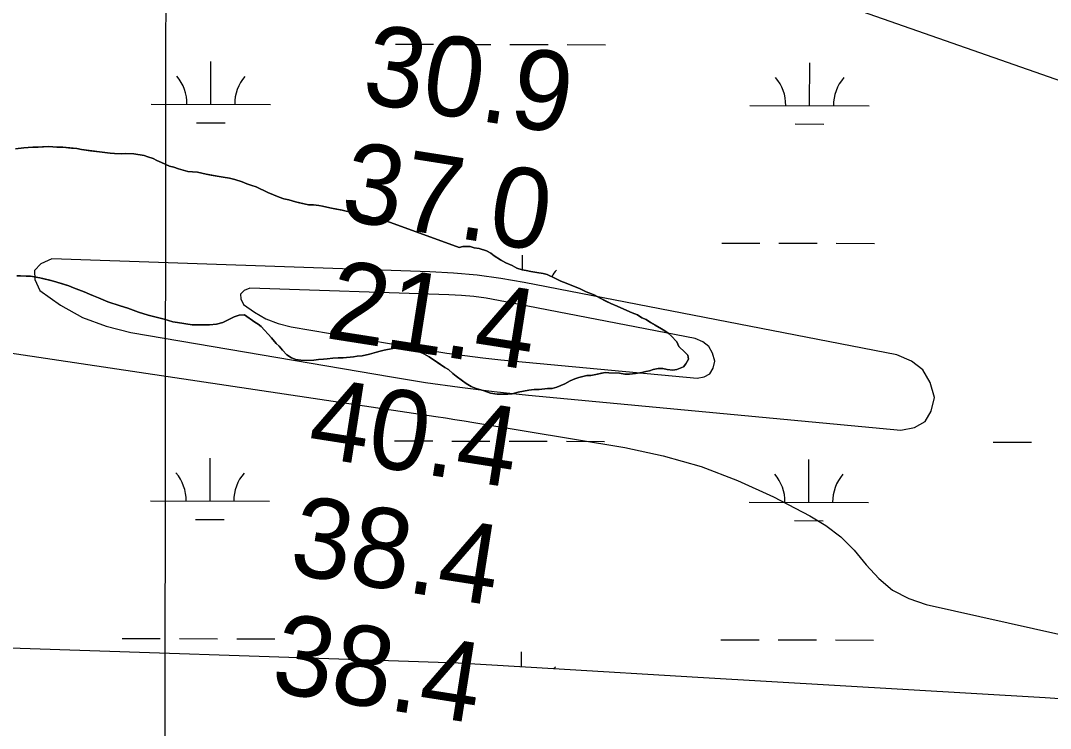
# Model space of a CAD drawing. Extents: x 3219052 to 3256913, y 800770 to 826146.
# Drawn here: x 3233583 to 3234446, y 813174 to 813768 of the extents above; entities that cross this region are included whole.
import ezdxf

# ---------------------------------------------------------------- set-up
doc = ezdxf.new("R2010")
doc.units = 0
for name, color, linetype in [('V-GRID-MAJR', 7, 'Continuous'), ('V-RIVR-RANG', 7, 'Continuous'), ('V-SITE-VEGE', 7, 'Continuous'), ('V-TOPO-MAJR', 7, 'Continuous'), ('V-TOPO-MINR', 7, 'Continuous'), ('V-TOPO-SHOR', 7, 'Continuous'), ('V-WETL-SWMP', 7, 'Continuous')]:
    doc.layers.add(name, color=color, linetype=linetype)

msp = doc.modelspace()

# ---------------------------------------------------------------- linework, layer by layer
at = {"layer": 'V-GRID-MAJR'}
msp.add_spline([(3233694.76, 806171.3), (3233702.69, 812230.43), (3233710.62, 818292.64), (3233718.56, 824354.89), (3233718.56, 824357.93)], degree=3, dxfattribs=at)
at = {"layer": 'V-SITE-VEGE'}
for points in [[(3233950.31, 813577.73), (3233886.64, 813600.99), (3233877.88, 813602.74), (3233873.82, 813604.08), (3233860.68, 813607.17), (3233855.67, 813608.21), (3233852.23, 813609.22), (3233843.14, 813610.66), (3233839.39, 813611.68), (3233832.5, 813613.07), (3233828.11, 813613.47), (3233824.02, 813613.56), (3233813.07, 813615.97), (3233807.44, 813617.66), (3233803.38, 813618.68), (3233799.32, 813620.02), (3233789.96, 813623.97), (3233780, 813628.57), (3233776.56, 813629.9), (3233772.19, 813631.24), (3233768.45, 813632.89), (3233762.21, 813634.9), (3233757.82, 813635.93), (3233752.5, 813636.66), (3233749.05, 813637.36), (3233738.08, 813639.15), (3233730.89, 813640.86), (3233722.73, 813641.65), (3233714.91, 813643.7), (3233711.17, 813645.03), (3233707.42, 813646.04), (3233700.87, 813649), (3233696.82, 813650.66), (3233693.71, 813652.29), (3233689.34, 813653.95), (3233686.22, 813654.95), (3233677.44, 813656.39), (3233670.84, 813656.52), (3233667.07, 813656.27), (3233661.42, 813656.7), (3233657.65, 813656.78), (3233648.87, 813657.89), (3233633.82, 813660.08), (3233629.75, 813660.79), (3233618.14, 813661.96), (3233613.11, 813662.06), (3233606.21, 813662.51), (3233585.44, 813661.35), (3233578.5, 813660.55)], [(3233832.45, 813483.88), (3233839.69, 813484.36), (3233844.42, 813484.9), (3233852.92, 813485.35), (3233861.73, 813486.12), (3233864.89, 813486.69), (3233868.98, 813486.92), (3233874.98, 813488.38), (3233880.99, 813490.14), (3233884.14, 813490.71), (3233887.3, 813491.59), (3233894.56, 813493.02), (3233900.23, 813493.53), (3233906.19, 813493.1), (3233910.58, 813492.39), (3233914.95, 813491.04), (3233920.57, 813488.73), (3233925.23, 813486.12), (3233938.25, 813477.06), (3233941.36, 813475.43), (3233945.07, 813472.21), (3233947.86, 813469.96), (3233956.22, 813463.82), (3233960.26, 813461.22), (3233964.62, 813459.56), (3233971.19, 813457.54), (3233976.49, 813455.56), (3233982.13, 813454.81), (3233990.93, 813454.64), (3233994.71, 813455.19), (3233999.77, 813456.35), (3234008.6, 813458.06), (3234013.02, 813458.6), (3234017.42, 813458.83), (3234024.35, 813459.64), (3234028.12, 813459.56), (3234032.23, 813460.73), (3234038.89, 813463.43), (3234043.34, 813465.86), (3234047.15, 813467.67), (3234050.63, 813468.86), (3234057.26, 813470.3), (3234060.72, 813470.55), (3234064.82, 813471.41), (3234072.71, 813472.82), (3234075.85, 813472.76), (3234084.64, 813472.27), (3234089.03, 813471.56), (3234093.11, 813471.47), (3234098.15, 813472), (3234103.51, 813472.84), (3234106.68, 813473.72), (3234109.83, 813474.29), (3234113, 813475.48), (3234117.1, 813476.34), (3234120.87, 813476.27), (3234124.63, 813475.57), (3234129.33, 813474.84), (3234132.8, 813475.4), (3234138.19, 813477.81), (3234140.13, 813480.29), (3234142.4, 813484.01), (3234141.84, 813487.48), (3234139.38, 813490.04), (3234134.44, 813494.86), (3234132.63, 813498.67), (3234128.02, 813503.79), (3234125.55, 813506.04), (3234122.76, 813507.98), (3234110.64, 813514.82), (3234106.91, 813517.41), (3234103.48, 813518.73), (3234099.76, 813521.32), (3234095.39, 813522.98), (3234090.72, 813524.96), (3234077.32, 813530.88), (3234067.98, 813535.47), (3234063.94, 813537.75), (3234061.14, 813539.06), (3234056.77, 813540.72), (3234051.16, 813543.35), (3234047.42, 813544.68), (3234039.94, 813547.97), (3234035.57, 813549.63), (3234030.58, 813551.93), (3234024.05, 813555.2), (3234015.28, 813556.95), (3234010.27, 813557.68), (3234003.06, 813559.08), (3233998.69, 813560.42), (3233994.65, 813562.7), (3233989.35, 813565.01), (3233984.99, 813567.3), (3233979.72, 813570.86), (3233976.94, 813573.11), (3233973.2, 813575.07), (3233966.96, 813577.08), (3233962.88, 813577.48), (3233959.44, 813578.49), (3233953.47, 813578.61), (3233950.31, 813577.73)], [(3233579.54, 813553.96), (3233590.85, 813553.74), (3233598.68, 813552.33), (3233610.25, 813549.58), (3233623.06, 813545.56), (3233627.12, 813543.9), (3233635.85, 813540.59), (3233643.65, 813537.29), (3233648.01, 813535.63), (3233655.81, 813532.33), (3233666.12, 813528.98), (3233672.67, 813526.97), (3233681.41, 813523.65), (3233689.53, 813520.97), (3233698.61, 813518.91), (3233702.98, 813517.56), (3233710.17, 813515.54), (3233714.24, 813514.83), (3233726.46, 813513.02), (3233736.21, 813512.82), (3233740.93, 813513.04), (3233746.91, 813513.55), (3233752.28, 813515.01), (3233761.8, 813519.54), (3233765.92, 813521.03), (3233770.33, 813521.26), (3233779, 813515.11), (3233781.8, 813513.49), (3233784.28, 813511.55), (3233792.89, 813501.95), (3233796.88, 813497.16), (3233799.35, 813494.9), (3233802.11, 813491.71), (3233805.81, 813487.86), (3233809.85, 813485.27), (3233813.28, 813483.94), (3233817.67, 813483.22), (3233822.69, 813483.13), (3233828.35, 813483.33), (3233832.45, 813483.88)]]:
    msp.add_lwpolyline(points, dxfattribs=at)
at = {"layer": 'V-TOPO-MAJR'}
msp.add_lwpolyline([(3233950.8, 813460.53), (3233979.53, 813457.06), (3234008.33, 813454.02), (3234320.46, 813424.64), (3234331.9, 813426.92), (3234340.83, 813431.79), (3234345.99, 813440.56), (3234348.64, 813451.92), (3234345.07, 813464.65), (3234339.05, 813475.22), (3234329.35, 813482.57), (3234317.2, 813487.78), (3234004.79, 813548.52), (3233985.15, 813551.86), (3233965.43, 813554.57), (3233945.61, 813556.34), (3233925.72, 813557.48), (3233608.84, 813568.14), (3233599.73, 813564.06), (3233594.39, 813558.54), (3233594.69, 813550.87), (3233598.76, 813541.75), (3233616.17, 813529.43), (3233634.51, 813519.13), (3233654.24, 813511.85), (3233674.91, 813506.58), (3233893.55, 813469.21), (3233922.15, 813464.66), (3233950.8, 813460.53)], dxfattribs=at)
at = {"layer": 'V-TOPO-MINR'}
for points in [[(3233954.92, 813487.1), (3233970.06, 813485.27), (3233985.24, 813483.67), (3234149.71, 813468.19), (3234155.74, 813469.39), (3234160.45, 813471.96), (3234163.17, 813476.58), (3234164.56, 813482.56), (3234162.68, 813489.27), (3234159.51, 813494.84), (3234154.39, 813498.72), (3234147.99, 813501.46), (3233983.37, 813533.47), (3233973.02, 813535.23), (3233962.63, 813536.66), (3233952.19, 813537.59), (3233941.7, 813538.19), (3233774.73, 813543.81), (3233769.92, 813541.66), (3233767.11, 813538.75), (3233767.27, 813534.7), (3233769.42, 813529.9), (3233778.59, 813523.41), (3233788.25, 813517.98), (3233798.65, 813514.14), (3233809.55, 813511.37), (3233924.75, 813491.68), (3233939.82, 813489.28), (3233954.92, 813487.1)], [(3233506.07, 813499.63), (3233930.82, 813436.08), (3233938.74, 813434.87), (3233946.66, 813433.64), (3233954.57, 813432.38), (3233962.48, 813431.08), (3234089.1, 813410.07), (3234121.4, 813403.13), (3234153.04, 813394.23), (3234183.71, 813382.39), (3234213.72, 813368.58), (3234244.1, 813352.83), (3234257.66, 813344.52), (3234270.26, 813335.09), (3234281.39, 813323.98), (3234291.55, 813311.74), (3234301.98, 813300.17), (3234313.63, 813290.46), (3234327.12, 813283.52), (3234341.84, 813278.43), (3234545.44, 813232.72)]]:
    msp.add_lwpolyline(points, dxfattribs=at)
at = {"layer": 'V-TOPO-SHOR'}
for points in [[(3233578.5, 813660.55), (3233585.44, 813661.35), (3233588.9, 813661.6), (3233592.99, 813661.83), (3233597.4, 813662.06), (3233606.21, 813662.51), (3233613.11, 813662.06), (3233618.14, 813661.96), (3233625.35, 813661.19), (3233629.75, 813660.79), (3233633.82, 813660.08), (3233641.34, 813658.99), (3233648.87, 813657.89), (3233657.65, 813656.78), (3233661.42, 813656.7), (3233667.07, 813656.27), (3233670.84, 813656.52), (3233677.44, 813656.39), (3233686.22, 813654.95), (3233689.34, 813653.95), (3233693.71, 813652.29), (3233696.82, 813650.66), (3233700.87, 813649), (3233707.42, 813646.04), (3233711.17, 813645.03), (3233714.91, 813643.7), (3233718.98, 813642.67), (3233722.73, 813641.65), (3233726.81, 813641.26), (3233730.89, 813640.86), (3233738.08, 813639.15), (3233742.47, 813638.43), (3233749.05, 813637.36), (3233752.5, 813636.66), (3233757.82, 813635.93), (3233762.21, 813634.9), (3233768.45, 813632.89), (3233772.19, 813631.24), (3233776.56, 813629.9), (3233780, 813628.57), (3233789.96, 813623.97), (3233799.32, 813620.02), (3233803.38, 813618.68), (3233807.44, 813617.66), (3233813.07, 813615.97), (3233816.51, 813615.27), (3233824.02, 813613.56), (3233828.11, 813613.47), (3233832.5, 813613.07), (3233835.63, 813612.38), (3233839.39, 813611.68), (3233843.14, 813610.66)], [(3233843.14, 813610.66), (3233847.53, 813609.94), (3233852.23, 813609.22), (3233855.67, 813608.21), (3233860.68, 813607.17), (3233866.31, 813605.8), (3233873.82, 813604.08), (3233877.88, 813602.74), (3233882.89, 813601.7), (3233886.64, 813600.99), (3233950.31, 813577.73)], [(3233950.31, 813577.73), (3233953.47, 813578.61), (3233959.44, 813578.49), (3233962.88, 813577.48), (3233966.96, 813577.08), (3233973.2, 813575.07), (3233976.94, 813573.11), (3233979.72, 813570.86), (3233984.99, 813567.3), (3233989.35, 813565.01), (3233994.65, 813562.7), (3233998.69, 813560.42), (3234003.06, 813559.08), (3234006.51, 813558.38), (3234010.27, 813557.68), (3234015.28, 813556.95), (3234020.6, 813555.9), (3234024.05, 813555.2), (3234030.58, 813551.93), (3234035.57, 813549.63), (3234039.94, 813547.97), (3234047.42, 813544.68), (3234051.16, 813543.35), (3234056.77, 813540.72), (3234061.14, 813539.06), (3234063.94, 813537.75), (3234067.98, 813535.47), (3234073.27, 813532.85), (3234077.32, 813530.88), (3234082.62, 813528.58), (3234090.72, 813524.96), (3234095.39, 813522.98), (3234099.76, 813521.32), (3234103.48, 813518.73), (3234106.91, 813517.41), (3234110.64, 813514.82), (3234114.68, 813512.54), (3234119.96, 813509.61), (3234122.76, 813507.98), (3234125.55, 813506.04), (3234128.02, 813503.79), (3234132.63, 813498.67), (3234134.44, 813494.86), (3234139.38, 813490.04), (3234141.84, 813487.48), (3234142.4, 813484.01), (3234140.13, 813480.29), (3234138.19, 813477.81), (3234132.8, 813475.4), (3234129.33, 813474.84), (3234124.63, 813475.57), (3234120.87, 813476.27), (3234117.1, 813476.34), (3234113, 813475.48), (3234109.83, 813474.29), (3234106.68, 813473.72), (3234103.51, 813472.84), (3234098.15, 813472), (3234093.11, 813471.47), (3234089.03, 813471.56), (3234084.64, 813472.27), (3234075.85, 813472.76), (3234072.71, 813472.82), (3234069.55, 813472.26), (3234064.82, 813471.41), (3234060.72, 813470.55), (3234057.26, 813470.3), (3234050.63, 813468.86), (3234047.15, 813467.67), (3234043.34, 813465.86), (3234038.89, 813463.43), (3234032.23, 813460.73), (3234028.12, 813459.56), (3234024.35, 813459.64), (3234017.42, 813458.83), (3234013.02, 813458.6), (3234008.6, 813458.06), (3234004.18, 813457.21), (3233999.77, 813456.35), (3233994.71, 813455.19), (3233990.93, 813454.64), (3233982.13, 813454.81), (3233976.49, 813455.56), (3233971.19, 813457.55), (3233964.62, 813459.56), (3233960.26, 813461.22), (3233956.22, 813463.82), (3233953.12, 813466.08), (3233947.86, 813469.96), (3233945.07, 813472.21), (3233941.36, 813475.43), (3233938.25, 813477.06), (3233934.53, 813479.65), (3233925.23, 813486.12), (3233920.57, 813488.73), (3233914.95, 813491.04), (3233910.58, 813492.39), (3233906.19, 813493.1), (3233900.23, 813493.53), (3233894.56, 813493.02), (3233887.3, 813491.59)], [(3233887.3, 813491.59), (3233884.14, 813490.71), (3233880.99, 813490.14), (3233874.98, 813488.38), (3233868.98, 813486.92), (3233864.89, 813486.69), (3233861.73, 813486.12), (3233852.92, 813485.35), (3233848.82, 813485.12), (3233844.42, 813484.9), (3233839.69, 813484.36), (3233836.54, 813484.11), (3233832.45, 813483.88), (3233828.35, 813483.33), (3233822.69, 813483.13), (3233817.67, 813483.22), (3233813.28, 813483.94), (3233809.85, 813485.27), (3233805.81, 813487.86), (3233802.11, 813491.71), (3233799.35, 813494.9), (3233796.88, 813497.16), (3233792.89, 813501.95), (3233784.28, 813511.55), (3233781.8, 813513.49), (3233779, 813515.11), (3233770.33, 813521.26), (3233765.92, 813521.03), (3233761.8, 813519.54), (3233752.28, 813515.01), (3233746.91, 813513.55), (3233740.93, 813513.04), (3233736.21, 813512.82), (3233726.46, 813513.01), (3233714.24, 813514.83), (3233710.17, 813515.54), (3233702.98, 813517.56), (3233698.61, 813518.91), (3233689.53, 813520.97), (3233681.41, 813523.65), (3233672.67, 813526.97), (3233666.12, 813528.98), (3233655.81, 813532.33), (3233651.75, 813533.98), (3233648.01, 813535.63), (3233643.65, 813537.29), (3233640.53, 813538.61), (3233635.85, 813540.59), (3233627.12, 813543.9), (3233623.06, 813545.56), (3233617.75, 813547.23), (3233610.25, 813549.58), (3233607.12, 813550.27), (3233598.68, 813552.33), (3233590.85, 813553.74), (3233587.39, 813553.81), (3233582.68, 813553.9), (3233579.54, 813553.96)]]:
    msp.add_lwpolyline(points, dxfattribs=at)
at = {"layer": 'V-WETL-SWMP'}
for p, q in [((3233896.8, 813748.25), (3233928.8, 813748.18)), ((3233944.8, 813748.15), (3233976.8, 813748.08)), ((3233992.8, 813748.05), (3234024.8, 813747.98)), ((3234040.8, 813747.95), (3234072.8, 813747.88)), ((3233742.1, 813697.83), (3233742.18, 813733.83)), ((3234244.01, 813696.78), (3234244.09, 813732.78)), ((3233692.1, 813697.94), (3233792.1, 813697.73)), ((3234194.01, 813696.88), (3234294.01, 813696.67)), ((3233730.07, 813682.43), (3233754.07, 813682.38)), ((3234231.98, 813681.37), (3234255.98, 813681.32)), ((3234170.36, 813581.5), (3234202.36, 813581.44)), ((3234218.36, 813581.4), (3234250.36, 813581.33)), ((3234266.36, 813581.3), (3234298.36, 813581.23)), ((3234003.25, 813559.02), (3234003.28, 813571.42)), ((3233896.1, 813415.58), (3233928.1, 813415.51)), ((3233944.1, 813415.48), (3233976.1, 813415.41)), ((3233992.1, 813415.37), (3234024.1, 813415.31)), ((3234040.1, 813415.27), (3234072.1, 813415.21)), ((3234398.01, 813414.52), (3234430.01, 813414.46)), ((3233741.41, 813365.16), (3233741.48, 813401.16)), ((3234243.31, 813364.11), (3234243.39, 813400.11)), ((3233691.41, 813365.26), (3233791.41, 813365.05)), ((3234193.31, 813364.21), (3234293.31, 813364)), ((3233729.37, 813349.75), (3233753.37, 813349.7)), ((3234231.28, 813348.7), (3234255.28, 813348.65)), ((3233667.76, 813249.88), (3233699.76, 813249.81)), ((3233715.76, 813249.78), (3233747.76, 813249.71)), ((3233763.76, 813249.68), (3233795.76, 813249.61)), ((3234169.66, 813248.83), (3234201.66, 813248.76)), ((3234217.66, 813248.73), (3234249.66, 813248.66)), ((3234265.66, 813248.63), (3234297.66, 813248.56)), ((3234002.55, 813226), (3234002.58, 813238.75))]:
    msp.add_line(p, q, dxfattribs=at)
for points in [[(3232589.14, 814286.39), (3233211.38, 813982.24), (3233471.85, 813837.41), (3233703.38, 813779.48), (3233963.85, 813779.48), (3234195.38, 813808.45), (3234484.8, 813707.06), (3234687.39, 813649.13), (3234861.03, 813692.58), (3235032.69, 813819.76), (3235126.63, 813828.41), (3235146.41, 813856.84), (3235150.45, 813909.83), (3234962.33, 813967.76), (3234788.68, 814083.62), (3234745.27, 814228.45), (3234774.21, 814329.84), (3234803.15, 814518.12)], [(3233950.31, 813577.73), (3233886.64, 813600.99), (3233882.89, 813601.7), (3233877.88, 813602.74), (3233873.82, 813604.08), (3233866.31, 813605.8), (3233860.67, 813607.17), (3233855.67, 813608.21), (3233852.23, 813609.22), (3233847.53, 813609.94), (3233843.14, 813610.66), (3233839.39, 813611.68), (3233835.63, 813612.38), (3233832.5, 813613.07), (3233828.11, 813613.47), (3233824.02, 813613.55), (3233816.51, 813615.27), (3233813.07, 813615.97), (3233807.44, 813617.66), (3233803.38, 813618.68), (3233799.32, 813620.02), (3233789.96, 813623.97), (3233780, 813628.57), (3233776.57, 813629.9), (3233772.19, 813631.24), (3233768.45, 813632.89), (3233762.21, 813634.9), (3233757.82, 813635.93), (3233752.5, 813636.66), (3233749.05, 813637.36), (3233742.47, 813638.43), (3233738.08, 813639.15), (3233730.89, 813640.86), (3233726.81, 813641.26), (3233722.73, 813641.65), (3233718.98, 813642.67), (3233714.91, 813643.7), (3233711.17, 813645.03), (3233707.42, 813646.04), (3233700.87, 813649), (3233696.82, 813650.66), (3233693.71, 813652.29), (3233689.34, 813653.95), (3233686.22, 813654.95), (3233677.44, 813656.38), (3233670.84, 813656.52), (3233667.07, 813656.28), (3233661.42, 813656.7), (3233657.65, 813656.78), (3233648.87, 813657.89), (3233641.34, 813658.99), (3233633.82, 813660.08), (3233629.75, 813660.79), (3233625.36, 813661.19), (3233618.14, 813661.96), (3233613.11, 813662.06), (3233606.21, 813662.51), (3233597.4, 813662.06), (3233592.99, 813661.83), (3233588.9, 813661.6), (3233585.44, 813661.35), (3233578.51, 813660.55)], [(3233994.65, 813562.7), (3233989.35, 813565.01), (3233984.99, 813567.29), (3233979.72, 813570.86), (3233976.94, 813573.11), (3233973.2, 813575.07), (3233966.96, 813577.08), (3233962.88, 813577.48), (3233959.44, 813578.49), (3233953.47, 813578.61), (3233950.31, 813577.73)], [(3233839.69, 813484.36), (3233844.42, 813484.9), (3233848.82, 813485.12), (3233852.91, 813485.35), (3233861.73, 813486.12), (3233864.89, 813486.69), (3233868.98, 813486.92), (3233874.98, 813488.38), (3233880.99, 813490.14), (3233884.14, 813490.71), (3233887.3, 813491.59), (3233894.56, 813493.02), (3233900.23, 813493.53), (3233906.19, 813493.1), (3233910.58, 813492.38), (3233914.95, 813491.04), (3233920.57, 813488.73), (3233925.23, 813486.12), (3233934.53, 813479.65), (3233938.25, 813477.06), (3233941.36, 813475.43), (3233945.07, 813472.21), (3233947.86, 813469.96), (3233953.12, 813466.08), (3233956.22, 813463.82), (3233960.26, 813461.22), (3233964.62, 813459.56), (3233971.19, 813457.55), (3233976.49, 813455.56), (3233982.13, 813454.81), (3233990.93, 813454.64), (3233994.71, 813455.19), (3233999.77, 813456.35), (3234004.19, 813457.21), (3234008.6, 813458.06), (3234013.02, 813458.6), (3234017.42, 813458.83), (3234024.35, 813459.64), (3234028.12, 813459.56), (3234032.23, 813460.74), (3234038.89, 813463.43), (3234043.34, 813465.86), (3234047.14, 813467.67), (3234050.63, 813468.86), (3234057.26, 813470.3), (3234060.72, 813470.55), (3234064.82, 813471.41), (3234069.55, 813472.26), (3234072.71, 813472.82), (3234075.85, 813472.76), (3234084.64, 813472.27), (3234089.03, 813471.56), (3234093.12, 813471.47), (3234098.16, 813472), (3234103.52, 813472.84), (3234106.68, 813473.72), (3234109.83, 813474.29), (3234113, 813475.48), (3234117.1, 813476.34), (3234120.87, 813476.27), (3234124.63, 813475.56), (3234129.33, 813474.84), (3234132.8, 813475.4), (3234138.19, 813477.81), (3234140.13, 813480.29), (3234142.4, 813484.01), (3234141.84, 813487.48), (3234139.38, 813490.05), (3234134.44, 813494.86), (3234132.63, 813498.67), (3234128.02, 813503.79), (3234125.55, 813506.04), (3234122.76, 813507.98), (3234119.96, 813509.61), (3234114.68, 813512.54), (3234110.64, 813514.82), (3234106.91, 813517.41), (3234103.48, 813518.73), (3234099.76, 813521.32), (3234095.39, 813522.98), (3234090.72, 813524.96), (3234082.62, 813528.58), (3234077.32, 813530.88), (3234073.27, 813532.85), (3234067.98, 813535.47), (3234063.94, 813537.75), (3234061.14, 813539.06), (3234056.77, 813540.72), (3234051.16, 813543.35), (3234047.42, 813544.68), (3234039.94, 813547.97), (3234035.57, 813549.63), (3234030.58, 813551.93), (3234024.05, 813555.2), (3234020.6, 813555.9), (3234015.28, 813556.95), (3234010.27, 813557.68), (3234006.51, 813558.38), (3234003.06, 813559.08), (3233998.69, 813560.42), (3233994.65, 813562.7)], [(3233579.54, 813553.96), (3233582.68, 813553.9), (3233587.39, 813553.81), (3233590.85, 813553.74), (3233598.68, 813552.33), (3233607.12, 813550.27), (3233610.25, 813549.58), (3233617.75, 813547.23), (3233623.06, 813545.56), (3233627.12, 813543.9), (3233635.85, 813540.59), (3233640.53, 813538.61), (3233643.65, 813537.29), (3233648.01, 813535.63), (3233651.75, 813533.98), (3233655.81, 813532.33), (3233666.11, 813528.98), (3233672.68, 813526.97), (3233681.41, 813523.65), (3233689.53, 813520.97), (3233698.61, 813518.91), (3233702.98, 813517.56), (3233710.17, 813515.54), (3233714.24, 813514.83), (3233726.47, 813513.01), (3233736.21, 813512.82), (3233740.93, 813513.04), (3233746.91, 813513.55), (3233752.28, 813515.01), (3233761.8, 813519.54), (3233765.92, 813521.03), (3233770.32, 813521.26), (3233779, 813515.11), (3233781.8, 813513.49), (3233784.28, 813511.55), (3233792.89, 813501.95), (3233796.88, 813497.16), (3233799.35, 813494.91), (3233802.12, 813491.71), (3233805.81, 813487.86), (3233809.85, 813485.27), (3233813.28, 813483.94), (3233817.67, 813483.22), (3233822.69, 813483.13), (3233828.35, 813483.33), (3233832.45, 813483.88), (3233836.54, 813484.11), (3233839.69, 813484.36)], [(3237234.22, 813214.64), (3236829.04, 813214.64), (3236669.86, 813156.71), (3236221.27, 813098.78), (3235772.68, 813127.74), (3235295.15, 813142.22), (3234861.03, 813171.19), (3234441.39, 813200.16), (3234150.43, 813217.29), (3234029.34, 813224.42), (3233949.38, 813229.12), (3233515.26, 813243.61), (3232921.97, 813243.61)]]:
    msp.add_lwpolyline(points, dxfattribs=at)
for centre, start, end in [((3233686.86, 813698.42), 359.1081, 40.65175), ((3233797.35, 813698.19), 139.10809, 180.65175), ((3234188.77, 813697.37), 359.1081, 40.65175), ((3234299.26, 813697.14), 139.10809, 180.65175), ((3234058.44, 813535.78), 139.10809, 150.22418), ((3233686.16, 813365.75), 359.1081, 40.65175), ((3233796.65, 813365.52), 139.10809, 180.65175), ((3234188.07, 813364.7), 359.1081, 40.65175), ((3234298.56, 813364.47), 139.10809, 180.65175), ((3234057.75, 813203.11), 139.10809, 142.81946)]:
    msp.add_arc(centre, 35.25, start, end, dxfattribs=at)

# ---------------------------------------------------------------- texts
at = {"layer": 'V-RIVR-RANG'}
for s, p in [('30.9', (3233867.36, 813699.72)), ('37.0', (3233849.47, 813601.31)), ('21.4', (3233837.04, 813502.03)), ('40.4', (3233821.75, 813403.21)), ('38.4', (3233806.47, 813304.38)), ('38.4', (3233791.18, 813205.56))]:
    msp.add_text(s, height=67, rotation=351.06833, dxfattribs=at).set_placement(p)

doc.saveas('drawing.dxf')
